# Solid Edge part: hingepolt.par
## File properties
Author: Mac
Template: Normal.par
Last saved by: Mac
Revision: 3
Application: Solid Edge
Density: 7750,000 kg/m^3
Accuracy: 0,990
Material: Stainless steel
Face Style: Steel
Fill Style: ANSI32(Steel)
Virtual Style: Stainless steel
Coef. of Thermal Exp: 1.6e-05
Thermal Conductivity: 17.0
Specific Heat: 502.0
Modulus of Elasticity: 193053196000.0
Poission's Ratio: 0.29
Yield Stress: 310264065.0
Ultimate Stress: 641212401.0
Elongation: 0.0
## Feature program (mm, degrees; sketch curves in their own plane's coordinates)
sketch for "unnamed RevolvedProtrusion 1" plane through (0, 0, 0) normal (0, 0, 1) x-axis (1, 0, 0)
  line (0, 0) -> (0.04, 0)
  arc centre (-0.0811, 0) radius 0.1211 from (0.04, 0) to (0, 0.09) ccw
  line (0, 0) -> (0, 0.09)
revolve "unnamed RevolvedProtrusion 1" add full turn 360 deg
sketch for "unnamed Protrusion 1" plane through (0, 0, 0) normal (-1, 0, 0) x-axis (0, -1, 0)
  circle centre (0, 0) radius 0.05
extrude "unnamed Protrusion 1" add finite 1.2 along +normal
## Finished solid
Body 1: solid body, 4 faces, 3 edges, 0 vertices.
  Faces by surface: plane 2, cylinder 1, sphere 1
  Edges by curve: circle 3
Bounding box of the edges (mm; curved faces can reach further): 1.200 x 0.180 x 0.180, from (-1.2, -0.09, -0.09) to (0, 0.09, 0.09).
Cylindrical faces by radius (mm): R0.05 x1
Spherical faces by radius (mm): R0.1211 x1
Planar faces by outward normal: -x 2
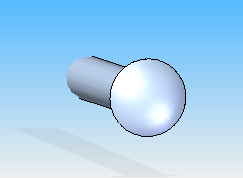
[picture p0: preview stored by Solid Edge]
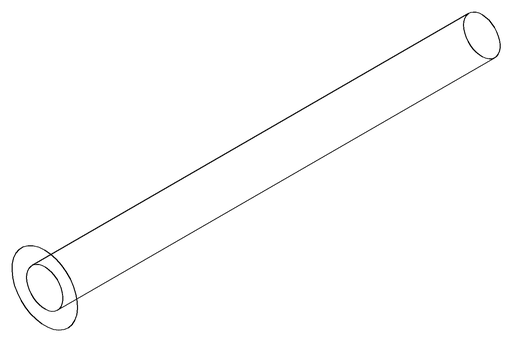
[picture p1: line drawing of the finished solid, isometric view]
